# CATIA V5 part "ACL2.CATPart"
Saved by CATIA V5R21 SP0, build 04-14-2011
Part number: ACL2.SLDPRT
Bounding box of the stored display mesh (mm): x -1.45 to 1.45, y -1 to 1, z -0.78 to 0
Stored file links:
  C:\Users\user\Desktop\CATIA文件\0-最新文件\ACL2\ACL2.CATPart
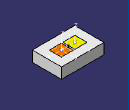
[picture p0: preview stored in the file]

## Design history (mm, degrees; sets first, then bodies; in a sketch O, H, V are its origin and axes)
AxisSystem1: origin (-0.465, 0, 0), X (1, 0, 0), Y (0, 1, 0), Z (0, 0, 1)
AxisSystem2: origin (0.465, 0, 0), X (1, 0, 0), Y (0, 1, 0), Z (0, 0, 1)
Set1
  DatumSurface1 to DatumSurface34
  Line1 to Line86: stored without definition
  Point1 "几何中心": type Between, FirstPoint vertex [face of DatumSurface7], SecondPoint vertex [face of DatumSurface7], Ratio 0.5
  Point2 "白光发光中心": type Between, FirstPoint vertex [face of DatumSurface7], SecondPoint vertex [face of DatumSurface7], Ratio 0.5
  Point3 "白光虚拟坐标": (0.0095, -0.0155, -0.0315), relative to Point2, in AxisSystem1
  Point4 "琥珀发光中心": type Between, FirstPoint vertex [face of DatumSurface1], SecondPoint vertex [face of DatumSurface1], Ratio 0.5
  Point5 "琥珀光虚拟坐标": (0.0127, -0.0051, -0.0357), relative to Point4, in AxisSystem2
Body1 (main body)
